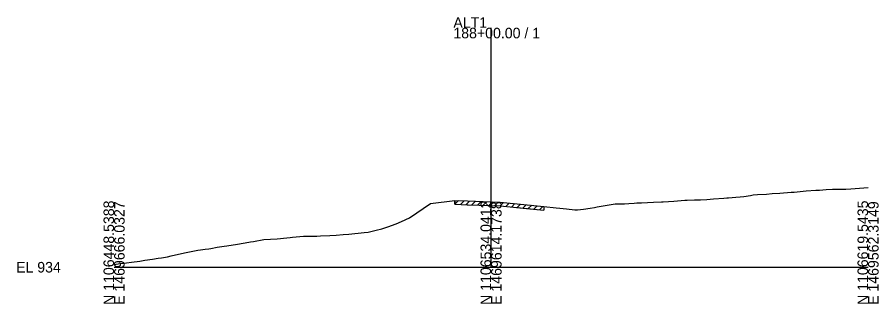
# Model space of a CAD drawing. Extents: x -26 to 2203, y -10 to 19568.
# Drawn here: x 1974.3 to 2202.8, y 9990.3 to 10066.3 of the extents above; entities that cross this region are included whole.
import ezdxf

# ---------------------------------------------------------------- set-up
doc = ezdxf.new("R2010")
doc.units = 0
for name, color, linetype in [('RD_GPK_XS_Cell', 7, 'Continuous'), ('RD_XS_ExGround', 7, 'Continuous'), ('RD_XS_ExPaveRet', 7, 'Continuous')]:
    doc.layers.add(name, color=color, linetype=linetype)

msp = doc.modelspace()

# ---------------------------------------------------------------- linework, layer by layer
at = {"layer": 'RD_GPK_XS_Cell'}
for p, q in [((2100, 10000), (2100, 10063.51)), ((2000, 10000), (2100, 10000)), ((2100, 10000), (2200, 10000))]:
    msp.add_line(p, q, dxfattribs=at)
at = {"layer": 'RD_XS_ExGround'}
msp.add_lwpolyline([(2000, 10000.74), (2001.12, 10000.9), (2003.27, 10001.15), (2004.63, 10001.31), (2006.81, 10001.65), (2008.14, 10001.83), (2010.19, 10002.15), (2011.65, 10002.37), (2012.6, 10002.53), (2014.19, 10002.8), (2015.16, 10003.04), (2018.67, 10003.78), (2019.11, 10003.87), (2022.18, 10004.51), (2022.93, 10004.59), (2024.17, 10004.77), (2025.11, 10004.91), (2025.68, 10005), (2027.3, 10005.29), (2029.19, 10005.58), (2029.95, 10005.68), (2032.7, 10006.09), (2035.74, 10006.66), (2036.21, 10006.75), (2036.94, 10006.86), (2039.72, 10007.33), (2041.52, 10007.47), (2043.23, 10007.57), (2045.86, 10007.82), (2046.74, 10007.89), (2047.31, 10007.97), (2050.25, 10008.21), (2051.32, 10008.2), (2053.09, 10008.25), (2053.75, 10008.28), (2054.78, 10008.32), (2057.26, 10008.44), (2058.88, 10008.52), (2060.77, 10008.65), (2062.24, 10008.8), (2066.36, 10009.22), (2067.39, 10009.31), (2069.53, 10009.85), (2070.98, 10010.22), (2071.3, 10010.31), (2072.61, 10010.75), (2074.81, 10011.5), (2076.23, 10012.12), (2078.36, 10013.07), (2083.92, 10016.94), (2090.38, 10017.7), (2093.71, 10017.58), (2100, 10017.35), (2102.42, 10017.26), (2110.43, 10016.49), (2114.01, 10016.13), (2117.23, 10015.78), (2118.21, 10015.66), (2120.01, 10015.46), (2122.19, 10015.18), (2122.93, 10015.18), (2124.54, 10015.44), (2126.29, 10015.7), (2127.44, 10015.88), (2127.76, 10015.93), (2128.12, 10016), (2132.96, 10016.79), (2135.38, 10016.85), (2136.5, 10016.9), (2137.96, 10016.98), (2138.68, 10017.04), (2139.87, 10017.11), (2141.47, 10017.21), (2143.05, 10017.26), (2145.23, 10017.31), (2145.65, 10017.33), (2148.49, 10017.52), (2151.44, 10017.76), (2152, 10017.8), (2153.97, 10017.86), (2155.51, 10017.91), (2157.22, 10018), (2159.01, 10018.12), (2161.78, 10018.33), (2162.52, 10018.38), (2163.01, 10018.43), (2164.89, 10018.57), (2166.03, 10018.67), (2167.07, 10018.77), (2168.79, 10019.05), (2169.54, 10019.16), (2170.7, 10019.25), (2173.05, 10019.42), (2174.58, 10019.54), (2176.56, 10019.68), (2179.61, 10019.88), (2180.36, 10019.93), (2183.58, 10020.22), (2186.14, 10020.4), (2187.08, 10020.45), (2188.91, 10020.58), (2190.59, 10020.68), (2191.93, 10020.71), (2194.1, 10020.73), (2195.47, 10020.79), (2197.71, 10021), (2200, 10021.17)], dxfattribs=at)
at = {"layer": 'RD_XS_ExPaveRet'}
for p, q in [((2090.38, 10017.7), (2090.38, 10016.7)), ((2090.38, 10016.69), (2090.38, 10017.69)), ((2090.38, 10016.69), (2091.34, 10017.66)), ((2090.38, 10016.71), (2093.88, 10016.59)), ((2090.38, 10016.71), (2090.38, 10016.71)), ((2090.38, 10016.69), (2093.63, 10016.57)), ((2091.88, 10016.66), (2092.82, 10017.6)), ((2093.38, 10016.6), (2094.32, 10017.55)), ((2093.88, 10016.59), (2100, 10016.36)), ((2094.88, 10016.53), (2095.84, 10017.49)), ((2096.38, 10016.47), (2097.34, 10017.44)), ((2097.88, 10016.42), (2098.84, 10017.38)), ((2099.38, 10016.36), (2100.34, 10017.33)), ((2100.88, 10016.31), (2101.84, 10017.27)), ((2102.38, 10016.25), (2103.29, 10017.17)), ((2103.88, 10016.12), (2104.78, 10017.03)), ((2105.38, 10015.97), (2106.28, 10016.88)), ((2106.88, 10015.83), (2107.78, 10016.74)), ((2108.38, 10015.68), (2109.28, 10016.59)), ((2093.63, 10016.57), (2100, 10016.34)), ((2100, 10016.34), (2102.42, 10016.25)), ((2102.42, 10016.28), (2110.28, 10015.52)), ((2102.42, 10016.26), (2110.43, 10015.49)), ((2109.88, 10015.54), (2110.78, 10016.44)), ((2110.28, 10015.52), (2114.01, 10015.15)), ((2110.5, 10015.47), (2114.01, 10015.12)), ((2111.38, 10015.41), (2112.26, 10016.3)), ((2112.88, 10015.26), (2113.76, 10016.15)), ((2114.01, 10016.15), (2114.01, 10015.15)), ((2114.01, 10016.13), (2114.01, 10015.13)), ((2114.01, 10015.12), (2114.01, 10015.12))]:
    msp.add_line(p, q, dxfattribs=at)

# ---------------------------------------------------------------- texts
at = {"layer": 'RD_GPK_XS_Cell'}
for s, p in [('ALT1', (2090, 10063.51)), ('188+00.00 / 1', (2090, 10060.71)), ('EL 934', (1974, 9998.6))]:
    msp.add_text(s, height=2.8, dxfattribs=at).set_placement(p)
for s, p in [('N 1106448.5388', (2000, 9990)), ('E 1469666.0327', (2002.8, 9990)), ('N 1106534.0412', (2100, 9990)), ('E 1469614.1738', (2102.8, 9990)), ('N 1106619.5435', (2200, 9990)), ('E 1469562.3149', (2202.8, 9990))]:
    msp.add_text(s, height=2.8, rotation=90, dxfattribs=at).set_placement(p)

doc.saveas('drawing.dxf')
